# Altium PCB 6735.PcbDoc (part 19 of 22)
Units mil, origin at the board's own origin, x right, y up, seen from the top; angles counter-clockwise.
Board outline 2641.73 x 5165.35 mil, 6 copper layers (Top, Inner Layer 2, Inner Layer 3, Inner Layer 4, Inner Layer 5, Bottom), stack 35.7 mil thick; 1011 components, 790 nets, 4118 pads, 9325 vias.
Unrouted connection lines stored in the file: 4610.
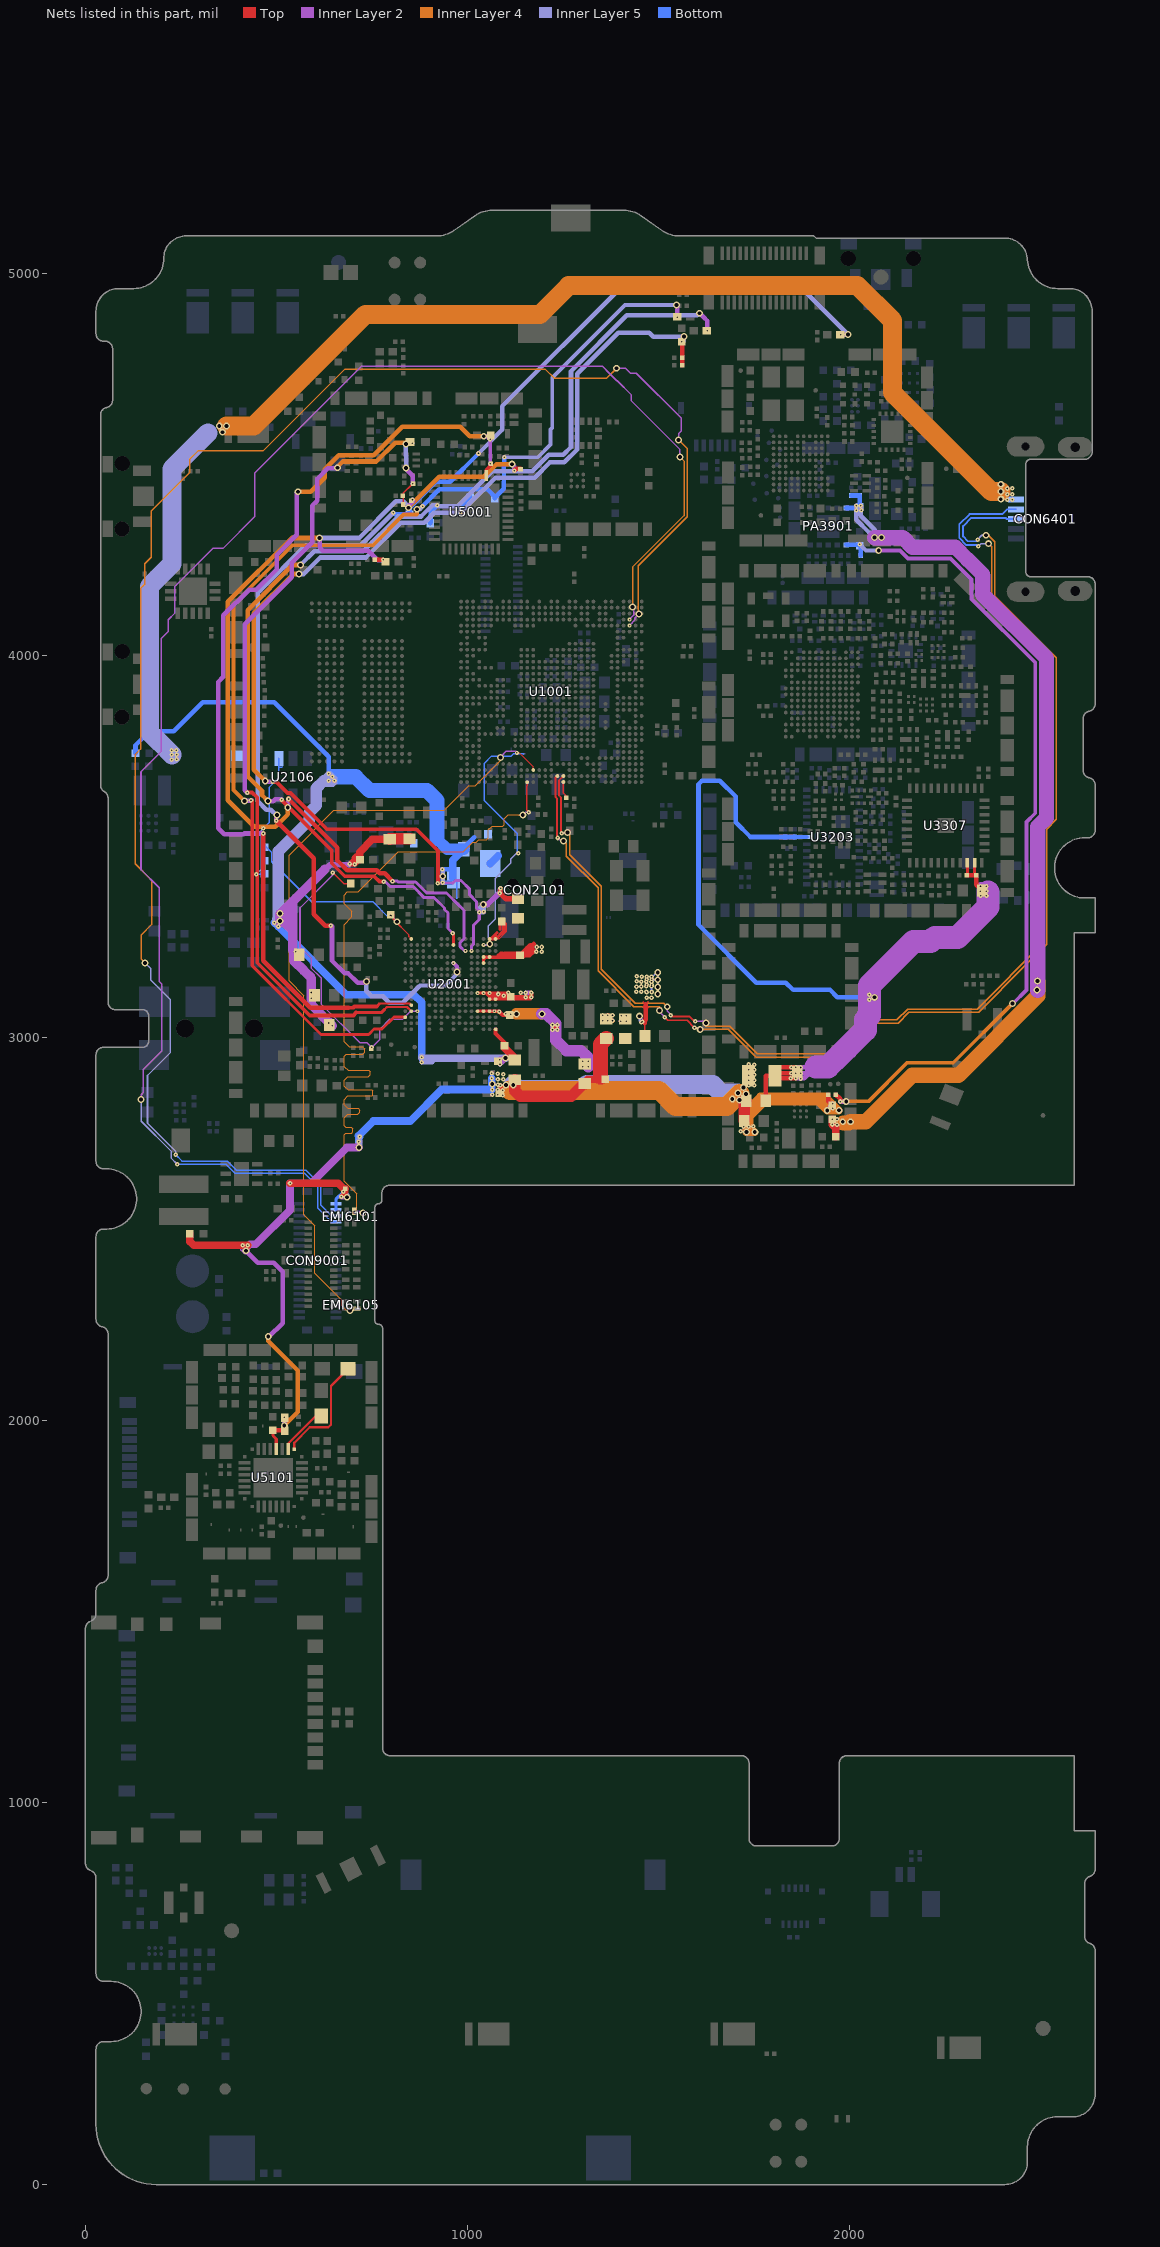
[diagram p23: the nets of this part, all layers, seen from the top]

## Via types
v1: diameter 12, hole 4, Top to Inner Layer 2, 3329 vias
v2: diameter 12, hole 4, Inner Layer 5 to Bottom, 3071 vias
v3: diameter 18, hole 10, Inner Layer 2 to Inner Layer 5, 1928 vias
v4: diameter 10, hole 4, Top to Inner Layer 2, 525 vias
v5: diameter 20, hole 12, Top to Bottom, 472 vias

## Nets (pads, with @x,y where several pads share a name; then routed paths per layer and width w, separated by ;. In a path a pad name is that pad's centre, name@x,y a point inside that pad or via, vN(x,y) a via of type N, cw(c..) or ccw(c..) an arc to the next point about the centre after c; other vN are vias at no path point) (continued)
TDP2: EMI6105.4 U1001.N3 | length 2074
  Top w3: U1001.N3@1171.71,3700.77 1171.71,3709.19 1135.41,3745.49 v4@1132.45,3745.49 ; v4@1132.45,3745.49 1129.95,3746.49 v4(1128.95,3745.49) v4@1132.45,3745.49
  Top w4: v1(707.46,2291.01) 707.46,2291.25 EMI6105.4@710.07,2291.25
  Inner Layer 2 w4: v3(692.08,2287.11) 695.99,2291.01 v1(707.46,2291.01) ; v3(1085.95,3733.49) 1088.95,3733.49 1088.95,3738.49 1100.95,3750.49 1125.95,3750.49 1129.95,3746.49 v4(1128.95,3745.49)
  Inner Layer 4 w3: v3(692.08,2287.11) 692.08,2288.41 681.58,2288.41 670.27,2299.72 670.27,2314.18 599.66,2384.8 599.66,2509.12 571.3,2537.48 571.3,3110.32 569.4,3112.22 532.58,3149.04 532.58,3478.11 650.01,3595.55 938.95,3595.55 1003.23,3659.83 1019.8,3659.83 1085.95,3725.98 v3(1085.95,3733.49)
TDP3: EMI6101.4 U1001.M1 | length 2022.2
  Top w4: v1(703.3,2547.09) EMI6101.4@703.8,2546.59 ; U1001.M1@1155.96,3669.27 1155.96,3660.61 1154.95,3659.6 1154.95,3595.44 v1(1160.3,3590.09)
  Inner Layer 2 w4: v1(703.3,2547.09) 715.3,2547.09 720.3,2542.09 v3(726.3,2542.09) ; v3(1144.3,3583.09) 1152.08,3590.86 1160.3,3590.86 v1(1160.3,3590.09)
  Inner Layer 4 w3: v3(726.3,2542.09) 716.95,2542.09 709.3,2549.74 709.3,2592.83 676.8,2625.33 676.8,2746.83 681.08,2751.11 696.23,2751.11 699.95,2754.83 699.95,2761.83 695.67,2766.11 680.95,2766.11 677.3,2769.76 677.3,2790.83 686.57,2800.11 712.08,2800.11 718.08,2806.11 718.08,2811.11 713.08,2816.11 686.35,2816.11 677.3,2825.16 677.3,2838.83 686.57,2848.11 750.23,2848.11 751.95,2849.83 751.95,2861.83 749.67,2864.11 687.35,2864.11 677.3,2874.16 677.3,2888.83 686.57,2898.11 739.73,2898.11 744.95,2903.33 744.95,2910.83 740.67,2915.11 687.08,2915.11 677.3,2924.89 677.3,2951.81 682.57,2957.09 725.31,2957.09 730.31,2962.09 730.31,2971.09 724.31,2977.09 689.57,2977.09 677.3,2989.36 677.3,3296.58 697.08,3316.36 697.08,3331.38 676.8,3351.66 676.8,3373.83 685.07,3382.11 713.18,3382.11 818.18,3487.11 988.08,3487.11 1013.06,3512.09 1021.86,3512.09 1028.86,3519.09 1049.3,3519.09 1054.3,3524.09 1054.3,3544.53 1063.86,3554.09 1092.3,3554.09 1095.3,3557.09 1095.3,3573.21 1105.57,3583.49 1133.35,3583.49 1133.75,3583.09 v3(1144.3,3583.09)
TX_N: L5102.1 U5101.17 | length 296.4
  Top w6: U5101.17@546.42,1923.99 546.42,1940.43 587.08,1981.09 635.21,1981.09 642.31,1988.19 642.31,2089.59 L5102.1@686.81,2134.09
TX_P: L5101.1 U5101.18 | length 131.9
  Top w6: U5101.18@530.67,1923.99 530.67,1938.82 601.31,2009.47 615.94,2009.47 615.94,2010.59 L5101.1@617.31,2010.59
URXD0: CON9001.5 U1001.AJ27 | length 4589.7
  Inner Layer 2 w4: v3(1389.76,4752.09) 1412.68,4752.09 1425.68,4739.09 1441.15,4739.09 1559.27,4620.97 1559.27,4588.64 1552.01,4581.38 v3(1552.01,4564.43) ; v4(1423.68,4078.72) 1430.95,4085.99 1430.95,4087.56 1437.11,4093.71 1437.11,4097.88 v3(1448.31,4109.09) v3@1448.54,4108.86
  Inner Layer 4 w4: v3(156.07,3196.06) 146.31,3205.81 146.31,3269.82 173.1,3296.61 173.1,3412.72 130.31,3455.51 130.31,3741.71 144.31,3755.71 144.31,4176.2 155.31,4187.2 155.31,4240.33 172.31,4257.33 172.31,4378.59 272.95,4479.23 272.95,4514.36 294.42,4535.83 464.56,4535.83 677.82,4749.09 1203.59,4749.09 1226.85,4725.83 1363.5,4725.83 v3(1389.76,4752.09) ; v3(1448.31,4109.09) 1446.19,4111.21 1446.19,4120.97 1446.31,4121.09 1446.31,4235.45 1574.31,4363.45 1574.31,4542.13 v3(1552.01,4564.43)
  Inner Layer 5 w4: v3(156.07,3196.06) 171.31,3180.81 171.31,3151 222.31,3100 222.31,2961.78 162.31,2901.78 162.31,2776.78 235.98,2703.11 v2(235.98,2694.33)
  Bottom w4: v2(235.98,2694.33) 252.61,2677.69 370.71,2677.69 394.31,2654.09 576.61,2654.09 615.31,2615.39 615.31,2563.07 638.29,2540.1 644.25,2534.16 655.53,2534.16 CON9001.5@655.53,2535.2
USB_DM: CON6401.2 U1001.V2 | length 3377
  Top w5: v1(1245.95,3535.09) 1243.95,3537.09 1243.95,3629.49 1238.95,3634.49 1238.95,3673.52 U1001.V2@1250.45,3685.02 ; v1(1531.14,3059.68) 1534.69,3056.13 1579.16,3056.13 1592.2,3043.09 v1(1595.82,3043.09)
  Inner Layer 2 w4: v1(1245.95,3535.09) 1245.95,3536.09 1260.95,3536.09 v3(1260.95,3537.09) ; v3(1522.21,3081.4) 1522.21,3070.19 1531.31,3061.09 v1(1531.14,3059.68) ; v1(1595.82,3043.09) 1619.31,3043.09 v3(1623.31,3039.09)
  Inner Layer 4 w3.5: v3(1260.95,3537.09) 1261.97,3537.09 1266.95,3532.11 1266.95,3479.19 1349.95,3396.19 1349.95,3179.24 1438.36,3090.83 1512.78,3090.83 v3(1522.21,3081.4) ; v3(1623.31,3039.09) 1623.31,3031.69 1624.3,3030.7 1685.59,3030.7 1758.17,2958.11 1944.3,2958.11 2033.16,3046.97 2122.41,3046.97 2150.81,3075.38 2333.04,3075.38 2506.18,3248.52 2506.18,3549.65 2531.81,3575.28 2531.81,3991.57 2370.81,4152.57 2370.81,4284.59 v3(2362.31,4293.09)
  Inner Layer 5 w4: v2(2336.31,4286.09) 2343.31,4293.09 v3(2362.31,4293.09)
  Bottom w4.6: CON6401.2@2422.36,4383.08 CON6401.2@2434.95,4383.08
  Bottom w5: v2(2336.31,4286.09) 2332.9,4289.5 2304.56,4289.5 2286.06,4308 2286.06,4343.58 2312.99,4370.5 2398.96,4370.5 2411.54,4383.08 CON6401.2@2434.95,4383.08
USB_DP: CON6401.3 U1001.U2 | length 3382.1
  Top w5: U1001.U2@1234.7,3685.02 1232.95,3685.01 1229.95,3682.01 1229.95,3630.49 1233.31,3627.12 1233.31,3523.09 v1(1235.31,3523.09) ; v1(1515.72,3054.07) 1523.71,3046.09 1574.46,3046.09 v1(1593.46,3027.09)
  Inner Layer 2 w4: v1(1235.31,3523.09) 1239.57,3518.83 1247.21,3518.83 v3(1250.95,3515.09) ; v3(1501.94,3071.59) 1497.2,3072.96 1497.06,3072.82 1506.78,3063.1 1506.78,3063.02 v1(1515.72,3054.07) ; v1(1593.46,3027.09) 1603.31,3027.09 v3(1608.31,3022.09)
  Inner Layer 4 w3.5: v3(1250.95,3515.09) 1258.4,3507.65 1258.4,3475.73 1341.45,3392.67 1341.45,3361.22 ; 1341.42,3361.19 1341.42,3175.91 1341.26,3175.91 1435.08,3082.08 1501.28,3082.08 1505.02,3078.34 1505.02,3077.1 1501.94,3074.02 v3(1501.94,3071.59) ; v3(1608.31,3022.09) 1608.41,3022.19 1682.08,3022.19 1754.65,2949.61 1947.82,2949.61 2036.68,3038.47 2125.93,3038.47 2154.33,3066.88 2336.59,3066.88 2456.85,3187.13 2514.68,3244.96 2514.68,3546.09 2540.31,3571.72 2540.31,3995.09 2379.31,4156.09 2379.31,4298.36 2362.59,4315.09 v3(2356.31,4315.09)
  Inner Layer 5 w4: v2(2334.31,4303.09) 2333.81,4303.59 2345.31,4315.09 v3(2356.31,4315.09)
  Bottom w5: v2(2334.31,4303.09) v2(2334.31,4303.09) 2330.63,4299.5 2308.7,4299.5 2296.14,4312.07 2296.14,4339.25 2317.39,4360.5 2408.05,4360.5 2411.06,4357.49 CON6401.3@2434.95,4357.49
USB_VRT_P0: R1201.1 U1001.V1 | length 43.9
  Top w4: U1001.V1@1250.45,3669.27 1250.45,3640.49 1257.95,3632.98 1257.95,3630.49 R1201.1@1257.95,3628.49
UTXD0: CON9001.7 U1001.AJ28 | length 4388.3
  Top w4: v4(1423.68,4094.47) 1423.61,4094.53 1422.25,4096.02 v4(1423.68,4094.47) v4(1423.68,4094.47)
  Inner Layer 2 w4: v3(145.71,2838.7) 145.71,2851.36 151.28,2856.94 151.28,2917.53 199.35,2965.6 199.35,3141.34 193.28,3147.42 193.28,3392.63 145.31,3440.59 145.31,3696.09 198.31,3749.09 198.31,4045.22 216.31,4063.22 216.31,4094.04 233.95,4111.68 233.95,4182 332.78,4280.83 359.57,4280.83 442.95,4364.21 442.95,4478 722.04,4757.09 1352.91,4757.09 1362.31,4747.68 1362.31,4747.01 1390.23,4719.09 1391.56,4719.09 1428.31,4682.34 1428.31,4666.69 1555.31,4539.69 v3(1555.31,4520.13) ; v4(1423.68,4094.47) 1423.26,4095.14 1433.95,4105.82 1433.95,4127.09 v3(1431.31,4127.09)
  Inner Layer 4 w4: v3(1431.31,4127.09) 1431.31,4231.78 1566.31,4366.78 1566.31,4509.13 v3(1555.31,4520.13)
  Inner Layer 5 w4: v3(145.71,2838.7) 145.71,2782.07 224,2703.77 224,2701.55 ; 223.98,2701.52 223.98,2685.61 v2(239.9,2669.68)
  Bottom w4: v2(239.9,2669.68) 367.4,2669.68 391,2646.09 573.3,2646.09 607.31,2612.08 607.31,2555.35 644.25,2518.41 655.53,2518.41 CON9001.7@655.53,2519.45
VBAT: C2007.1 C9001.1 CON2101.1 CON9001.1 CON9001.3 D2103.K R2036.1 R2037.1 R2045.1 R2047.1 R2048.2 R2098.1 R2099.1 R2135.2 R2140.2 R2308.1 R2316.1 R2405.1 R2408.1 R3239.2 SH2009.1 SH2010.1 SH2011.1 SH2012.1 SH2013.1 SH2014.1 SH5111.1 VR2101.1 | length 8783.8
  Top w4: R2308.1@272.37,2488.41 R2308.1@272.95,2487.83 ; v1(520.68,2007.69) 520.96,2007.41 SH5111.1@520.96,2006.49 ; v1(550.21,3225.31) 552.31,3226.09 559.36,3219.04 R2099.1@559.36,3217.83 ; v1(590.95,3103.83) 598.95,3111.83 R2037.1@599.36,3111.83 592.36,3118.83 v1(590.95,3118.83) ; v1(636.17,3039.02) 638.76,3039.02 R2098.1@643.95,3033.83 ; R2098.1@637.72,3033.83 R2098.1@643.95,3033.83 ; v1(691.1,3455.08) 691.1,3454.99 704.6,3454.99 v1(704.6,3454.89) ; R2048.2@1079.31,2938.76 R2048.2@1080.16,2938.91 ; v1(1084.08,2943.12) 1084.23,2942.98 R2048.2@1080.16,2938.91 ; v1(1084.61,2930.81) 1084.61,2934.47 R2048.2@1080.31,2938.76 ; SH2012.1@1120.31,3372.09 1123.44,3372.09 SH2012.1@1131.45,3364.08 1130.31,3362.94 SH2012.1@1130.31,3352.09 ; v1(1456.95,3041.83) 1458.45,3043.33 1463.72,3038.06 C2007.1@1463.72,3005.09 ; 1459.31,3079.09 1459.31,3081.68 1465.72,3088.09 ; 1459.31,3094.09 1465.31,3088.09 1465.72,3088.09 ; 1471.81,3094.09 1471.72,3094.09 ; 1472.31,3079.09 1465.72,3085.68 1465.72,3088.09 ; R3239.2@1722.31,2917.56 1734.63,2905.24 R3239.2@1734.63,2902.13 ; R3239.2@1735.08,2899.06 1735.08,2900.13 R3239.2@1735.08,2900.58 ; R2098.1@643.95,3033.83 v1(645.95,3031.83) 645.95,3032.83 644.95,3033.83 R2098.1@643.95,3033.83 ; R2048.2@1080.16,2938.91 1080.31,2938.91 R2048.2@1080.31,2938.76 ; R2048.2@1080.16,2938.91 R2048.2@1080.31,2938.76 ; 1465.72,3088.09 1471.72,3094.09 ; 1465.72,3088.09 1471.72,3094.09 ; R3239.2@1734.63,2902.13 v1(1735.08,2902.58) 1735.08,2901.75 1735.08,2901.03 R3239.2@1735.08,2900.58 ; R3239.2@1734.63,2902.13 R3239.2@1734.63,2900.58 R3239.2@1735.08,2900.58
  Top w10: v1(704.6,3454.89) v1@705.25,3455.09 ; v1@705.3,3455.13 705.16,3455.53 705.29,3455.1 705.56,3454.84 705.81,3455.09 716.81,3466.09 717.06,3466.34 R2045.1@717.31,3466.34
  Top w12: v1(669.29,2583.91) 682.34,2596.96 682.34,2603.11 C9001.1@679.95,2605.49 ; 717.31,3486.09 702.11,3470.89 702.11,3466.09 ; SH2014.1@1083.58,2855.15 1084.81,2855.15 v1(1084.81,2876.65) ; v1(1084.14,3379.1) 1084.14,3380.83 v1@1085.95,3380.83 ; v1@1085.95,3391.13 v1@1085.95,3380.83 ; 1102.62,3364.08 v1@1085.95,3380.75 ; 1463.72,3038.06 1463.72,3045.59 1465.72,3047.59 1465.72,3088.09 ; v1(1735.08,2902.58) R3239.2@1735.47,2902.77 ; 702.11,3466.09 697.76,3461.74 v1(691.1,3455.08) 693.31,3455.09 705.25,3455.09 705.31,3455.09 705.81,3455.09 707.31,3455.09 R2045.1@718.31,3466.09 717.31,3466.09 716.81,3466.09 702.11,3466.09 ; v1@1085.95,3380.75 v1@1085.95,3380.83 ; v1@1085.95,3380.75 1086.03,3380.75 v1@1085.95,3380.83 ; R3239.2@1734.63,2900.58 1735.08,2900.13 1739.08,2896.13 1739.08,2885.58 1738.83,2886.45 1737.67,2890.35 1735.08,2899.06 R3239.2@1734.63,2900.58 ; R3239.2@1734.63,2900.58 1735.08,2901.75 1735.36,2902.47 R3239.2@1735.47,2902.77 ; R3239.2@1734.63,2900.58 1735.08,2901.03 R3239.2@1738.08,2904.03 ; R3239.2@1735.47,2902.77 1738.08,2909.58 R3239.2@1738.08,2904.03 ; R3239.2@1735.47,2902.77 R3239.2@1738.08,2904.03
  Top w15: v1@1085.95,3380.75 1085.45,3380.25 1085.45,3379.1 1100.47,3364.08 1102.62,3364.08 SH2012.1@1131.45,3364.08
  Top w20: R2308.1@272.95,2487.83 272.95,2467.5 282.95,2457.5 384.06,2457.5 ; v1(411.56,2457.5) 384.06,2457.5 ; v1(424.17,2457.63) 384.2,2457.63 384.06,2457.5 ; v1(535.24,2620.16) 661.16,2620.16 675.83,2605.49 C9001.1@679.95,2605.49 ; R2045.1@717.31,3466.09 717.31,3466.34 717.31,3486.09 750.91,3519.68 R2047.1@796.31,3519.68 ; SH2013.1@1118.95,2890.9 SH2013.1@1122.95,2890.9 ; SH2010.1@1306.31,2880.5 1306.31,2884.09 1314.31,2892.09 R2405.1@1360.31,2892.09
  Top w30: R2047.1@796.31,3519.68 796.31,3521.08 R2036.1@847.95,3521.08 ; SH2013.1@1122.95,2890.9 1122.95,2861.9 1138.02,2846.83 1270.64,2846.83 1304.31,2880.5 SH2010.1@1306.31,2880.5
  Top w40: 1347.31,2898.09 1347.31,2983.5 SH2009.1@1362.31,2998.5
  Inner Layer 2 w4: v1(411.56,2457.5) 405.91,2451.84 405.91,2446.02 408.64,2443.28 v3(419.64,2443.28) ; v3(508.77,3305.97) 500.99,3313.75 500.99,3317.15 v3(509.03,3325.18) ; 520.95,3301.93 539.2,3301.93 542.31,3298.81 ; v1@545.45,3226.09 550.21,3226.09 v1(550.21,3225.31) ; v1@636.17,3041.61 v1(636.17,3039.02) 644.66,3030.53 v1(645.95,3031.83) ; v1@1084.81,2876.61 v3(1100.35,2876.57) ; v3(1449.95,3056.83) 1456.95,3049.83 v1(1456.95,3041.83) ; v1(1481.95,3153.49) 1481.95,3152.79 v3@1497.31,3152.79 ; v3(1497.31,3133.09) v3(1497.31,3152.09) v3@1497.31,3152.79 ; v3(1497.31,3171.09) v3@1497.31,3152.79
  Inner Layer 2 w12: v3(419.64,2443.28) 451.14,2411.79 492.47,2411.79 515.99,2388.27 515.99,2253.9 479.75,2217.65 v3(478.31,2219.09) ; v3(520.31,1986.09) 520.68,1986.45 v1(520.68,2007.69) ; v1(669.29,2583.91) 669.29,2583.5 684.3,2583.5 v3(684.3,2583.09) ; v1@690.51,3453.56 691.85,3454.89 v1(704.6,3454.89) ; v1@1084.1,3380.83 v1(1084.14,3379.1) v1@1084.14,3380.83 ; v1@1085.95,3380.83 v1@1084.14,3380.83 ; v1(1085.96,3391.13) 1084.14,3389.3 v1@1084.14,3380.83 ; v3(1099.31,2947.15) v3@1099.31,2945.51 ; v3@1098.61,2944.81 1090.5,2936.7 v1(1084.61,2930.81) 1084.35,2930.81 1084.35,2943.12 v1(1084.08,2943.12) 1084.08,2944.81 v3@1098.61,2944.81 ; v3@1098.61,2944.81 v3@1099.31,2945.51 ; v3@1098.61,2944.81 1099.31,2944.81 v3@1099.31,2945.51
  Inner Layer 2 w15: 625.95,3440.83 628.31,3440.83 640.57,3453.09 690.51,3453.09 v1@690.51,3453.56 ; v3(1040.95,3348.83) 1052.1,3348.83 v1@1084.1,3380.83
  Inner Layer 2 w20: v3(419.64,2443.28) 419.64,2449.9 429.62,2459.88 445.39,2459.88 535.31,2549.81 535.31,2586.18 535.24,2586.26 v1(535.24,2620.16) 591.12,2620.16 684.05,2713.09 v3(715.31,2713.09) ; 542.31,3298.81 542.31,3299.99
  Inner Layer 2 w25: v3(509.03,3325.18) v3@510.3,3325.18 ; 542.31,3298.81 542.31,3280.56 ; 625.95,3440.83 542.31,3357.19 ; v1(645.95,3031.83) 637.47,3040.32 636.17,3041.61 590.95,3086.83 v1(590.95,3103.83) v1(590.95,3118.83) 590.95,3156.24 571.45,3175.74 571.45,3175.93 545.65,3201.74 545.45,3201.74 545.45,3226.09 542.31,3229.23 542.31,3280.56 ; v3@510.3,3325.18 v3@517.12,3325.18 ; v3@510.3,3325.18 509.67,3324.54 508.77,3323.65 v3(508.77,3305.97) 508.77,3301.93 520.95,3301.93 542.31,3280.56 ; v3@510.3,3325.18 521.12,3336 ; v3@517.12,3325.18 517.64,3325.18 521.12,3321.71 ; v3@517.12,3325.18 542.31,3299.99 542.31,3321.71 ; 521.12,3321.71 542.31,3321.71 ; 521.12,3321.71 521.12,3336 ; 521.12,3336 542.31,3357.19 ; 542.31,3321.71 542.31,3357.19
  Inner Layer 4 w12: v3(478.31,2219.09) 478.31,2206.98 555.44,2129.85 555.44,2021.22 v3(520.31,1986.09)
  Inner Layer 4 w50: 1111.31,2863.09 1111.57,2862.83 1500.86,2862.83 1543.33,2820.36 1677.71,2820.36 1703.11,2845.76 1710.11,2852.76 v3@1711.96,2854.62
  Inner Layer 5 w4: 494.47,3309.33 498.88,3313.75 500.99,3313.75 504.95,3309.79 508.06,3306.68 v2@498.62,3297.25 ; v2(504.28,3291.59) 504.28,3296.53 504.28,3301.48 v3(508.77,3305.97) ; 622.9,3672.44 v2(651.47,3672.44) ; v2(1480.95,3159.83) 1482.23,3158.55 1496.04,3172.36 v3(1497.31,3171.09)
  Inner Layer 5 w6: v3(1449.95,3056.83) 1449.95,3044.71 v2(1453.66,3041)
  Inner Layer 5 w12: v2(504.28,3291.59) v2@501.81,3294.06 ; v3(508.77,3305.97) 511.24,3303.5 504.28,3296.53 v2@501.81,3294.06 ; v3(509.03,3325.18) 507.67,3326.54 504.95,3323.82 494.47,3313.33 494.47,3309.33 v2(494.47,3301.33) v2(494.47,3301.33) 498.62,3297.25 499.34,3296.53 v2@501.81,3294.06 ; v2(674.95,2597.83) 675.96,2597.83 684.3,2589.49 v3(684.3,2583.09) ; v2(880.31,2949.15) v2(880.31,2936.65) 906.81,2936.65 917.31,2947.15 ; v2(933.95,3440.83) 934.45,3440.83 934.45,3432.83 ; v2(934.95,3405.83) v3(934.95,3422.83) ; 934.45,3432.83 934.95,3432.33 v3(934.95,3422.83) ; 934.45,3432.83 934.45,3422.83 v3(934.95,3422.83) ; v2(1029.95,3328.83) 1029.95,3337.83 v3(1040.95,3348.83) 1041.45,3348.83 1041.45,3329.83 v2(1041.95,3329.83) 1041.95,3328.83 v2(1029.95,3328.83)
  Inner Layer 5 w15: v3(715.31,2713.09) 716.21,2713.09 716.21,2741.14 v2(717.11,2741.14) ; 622.9,3668.3 627.16,3664.04 646.84,3664.04 651.47,3668.67 v2(651.47,3672.44) 651.47,3677.94 v2(646.19,3683.22) 638.62,3690.79 v2(636.32,3690.79) 635.4,3690.79 622.9,3678.29 622.9,3672.44 622.9,3668.3
  Inner Layer 5 w18: v3(715.31,2713.09) v2(715.32,2728.78)
  Inner Layer 5 w20: v2(880.31,2949.15) 882.31,2947.15 917.31,2947.15 v3(1099.31,2947.15)
  Inner Layer 5 w25: v3(508.77,3305.97) 508.77,3318.24 505.43,3321.58 504.95,3322.06 508.07,3325.18 v3(509.03,3325.18)
  Inner Layer 5 w30: v3@504.95,3309.79 504.95,3322.06 504.95,3323.82 504.95,3488.67 584.93,3568.65 584.93,3589.06 603.95,3608.09 603.95,3653.49 622.9,3672.44 623.76,3673.3 v2(637,3673.3) ; v3@508.06,3306.68 v3(508.77,3305.97)
  Inner Layer 5 w50: v3(1119.31,2877.09) 1119.31,2865.09 1298.79,2865.09 1311.79,2878.09 1641.31,2878.09 1663.84,2855.56 v3(1707.31,2855.56)
  Bottom w4: R2316.1@130.95,3744.49 R2316.1@131.31,3744.13 ; v2(715.32,2728.78) 716.21,2728.78 716.21,2740.24 716.21,2741.14 v2(717.11,2741.14) ; v2@879.52,2948.36 v2(880.31,2949.15) v2(880.31,2936.65) ; R2135.2@957.95,3407.83 957.95,3414.04 R2135.2@963.4,3419.49 ; R2135.2@960.95,3419.49 R2135.2@963.4,3419.49 ; R2135.2@960.95,3440.83 963.4,3438.38 R2135.2@963.4,3419.49 ; R2140.2@971.95,3365.49 971.95,3410.94 R2135.2@963.4,3419.49 ; v2(1480.95,3134.83) 1480.95,3122.83 v2(1481.95,3120.83)
  Bottom w8: CON9001.3@655.53,2550.95 CON9001.1@655.53,2566.7 655.95,2566.69 655.95,2578.83 v2(674.95,2597.83)
  Bottom w12: R2316.1@130.95,3744.49 130.95,3765.5 167.95,3802.5 230.72,3802.5 306.72,3878.5 494.06,3878.5 637,3735.56 v2@637,3690.79 ; v2(636.32,3690.79) v2@637,3690.79 ; v2(651.47,3672.44) 651.47,3673.3 v2(637,3673.3) ; v2@651.58,3683.62 647.33,3683.62 646.93,3683.22 v2(637,3673.3) ; v2(933.95,3440.83) R2135.2@960.95,3440.83 ; v2(934.95,3405.83) 957.95,3405.83 R2135.2@957.95,3407.83 ; D2103.K@989.95,3493.72 989.95,3497.65 1017.72,3525.42 ; v2(637,3673.3) v2@637,3690.79 ; v2(637,3673.3) v2@637,3690.79
  Bottom w20: v2@494.49,3301.35 v2(504.28,3291.59) ; v2(504.28,3291.59) 682.79,3113.08 859.2,3113.08 879.52,3092.75 v2@879.52,2948.36 ; v2(715.32,2728.78) 715.32,2739.35 716.21,2740.24 v2(717.11,2741.14) 714.56,2743.69 753.37,2782.5 849.69,2782.5 932.19,2865 1063.31,2865 v2(1063.31,2894.09) ; R2135.2@960.95,3419.49 960.95,3440.83 960.95,3464.72 974.32,3478.09 D2103.K@989.95,3493.72 D2103.K@989.95,3489.78 ; CON2101.1@1059.2,3456.21 CON2101.1@1079.95,3476.95
  Bottom w30: 919.75,3520.69 946.72,3493.72 D2103.K@989.95,3493.72
  Bottom w40: v2(646.19,3683.22) 646.93,3683.22 707.18,3683.22 742.96,3647.44 893.53,3647.44 919.75,3621.22 919.75,3520.69
  other v1: 1735.31,2876.56 1749.31,2876.56 1735.08,2889.58 1749.31,2889.56 1749.31,2903.56 1735.08,2916.58 1749.31,2916.56 1749.31,2929.56 1735.31,2930.56 1468.95,3105.49 1480.95,3105.49 1468.95,3119.49 1481.95,3119.49 1468.95,3139.49 1481.95,3139.49 1468.95,3153.49
  other v2: 1092.02,2849.95 1064.62,2851.13 1078.72,2851.6 1091.84,2862.93 1064.31,2864.09 1079.31,2864.09 1079.31,2877.09 1079.31,2892.09 1093.31,2892.09 1092.94,2905.36 1078.72,2906.57 1063.3,2907.41 1441.6,3120.71 1454.3,3120.7 1466.95,3120.83 1441.75,3134.3 1454.46,3134.5 1466.95,3134.83 1454.41,3147.45 1466.95,3146.83 1480.95,3146.83 1442.03,3148.48 1455.32,3159.99 1468.48,3159.81 1441.9,3161.29
  other v3: 1711.31,2837.56 1692.31,2840.56 1728.31,2853.56 1721.31,2870.56 1064.31,2879.09 1497.31,3115.09
VBAT_NFC: C5115.2 SH5111.2 U5101.20 | length 83.7
  Top w8: C5115.2@490.31,1973.09 490.45,1972.95 490.45,1959.28 499.17,1950.55 U5101.20@499.18,1923.99
  Top w12: C5115.2@490.31,1973.09 520.36,1973.09 SH5111.2@520.96,1972.49
VBAT_RF: C3239.1 C3248.1 C3249.1 C3324.1 C3339.1 C3348.1 R3239.1 R3901.1 U3203.8 U3307.9 U3307.10 | length 2818.9
  Top w4: R3239.1@1803.53,2900.58 1803.95,2900.16 R3239.1@1803.95,2892.96
  Top w8: U3307.9@2307.35,3458.15 C3348.1@2307.35,3427.28 ; U3307.10@2326.24,3458.15 2326.24,3430 C3324.1@2330.65,3425.59 ; C3348.1@2307.35,3427.28 C3348.1@2305.65,3425.59 2307.35,3425.59 C3348.1@2307.35,3427.28
  Top w12: R3901.1@1779.67,2835.58 1779.67,2899.72 1780.53,2900.58 R3239.1@1803.53,2900.58 R3239.1@1803.53,2907.92 ; R3239.1@1803.95,2892.96 1804.95,2893.96 v1(1857.95,2893.96) ; v1(1858.95,2907.93) v1(1846.44,2907.92) R3239.1@1803.53,2907.92 ; C3239.1@1858.95,2922.94 v1(1846.73,2922.92) 1814.87,2922.92 1803.53,2911.58 R3239.1@1803.53,2907.92 ; C3348.1@2307.35,3425.59 C3324.1@2330.65,3425.59 2330.65,3401.18 C3339.1@2346.24,3385.59
  Top w20: R3239.1@1803.53,2911.58 R3239.1@1803.53,2914.58
  Top w30: R3239.1@1803.53,2900.58 R3239.1@1805.53,2900.58
  Inner Layer 2 w4: 2051.65,3102.15 2055.65,3106.15 v3(2064.81,3106.15) ; v1(2357.28,3397.06) 2357.32,3397.02 2361.63,3392.71 v1@2361.63,3381.91
  Inner Layer 2 w12: v1(1857.95,2893.96) 1880.95,2893.96 1894.93,2907.93 ; v1(1858.95,2907.93) 1894.93,2907.93 ; v1(1858.95,2922.96) 1909.95,2922.96 ; 1910.95,2923.96 1909.95,2922.96 ; 1894.93,2907.93 1909.95,2922.96
  Inner Layer 2 w20: v1(2342.07,3371.61) 2341.91,3371.61 v1@2341.91,3396.48 ; v1(2357.07,3384.28) 2356.33,3383.54 v1@2342.81,3397.06 ; v1(2357.28,3397.06) v1@2342.81,3397.06 ; v1@2357.32,3371.72 v1@2357.32,3381.07 ; v1@2357.32,3397.02 v1@2357.32,3381.07 ; 2361.63,3376.76 v1@2357.32,3381.07 ; v1(2341.75,3396.64) v1@2342.18,3397.06 ; v1(2341.75,3396.64) 2341.91,3396.64 v1@2341.91,3396.48 ; v1(2341.75,3396.64) v1@2341.91,3396.48 ; v1(2341.75,3396.64) v1@2342.18,3397.06 ; v1@2341.91,3396.48 v1@2357.32,3381.07 ; v1@2342.18,3397.06 v1@2342.49,3397.37 ; v1@2342.18,3397.06 v1@2342.49,3397.37 ; v1@2342.18,3397.06 v1@2342.81,3397.06 ; v1@2342.49,3397.37 v1@2342.81,3397.06
  Inner Layer 2 w60: 1910.95,2923.96 1911.12,2924.13 1942.8,2924.13 1973.58,2954.91 1991.46,2972.79 1992.15,2972.79 2040.31,3020.95 2040.31,3047.25 2051.65,3058.59 2051.65,3102.15 2051.65,3106.15 2051.65,3137.55 2166.66,3252.56 2211.53,3252.56 2222.15,3263.18 2282.05,3263.18 2361.63,3342.75 2361.63,3371.72 2361.63,3376.76 v1@2361.63,3381.91
  Inner Layer 5 w12: v2(2050.31,3100.15) 2058.81,3100.15 v3(2064.81,3106.15) 2064.94,3106.28 2058.57,3112.65 v2(2050.31,3112.65) v2(2050.31,3100.15)
  Bottom w4: v2(2050.31,3100.15) 2050.31,3098.65 2047.31,3098.65 2045.81,3100.15 2039.31,3106.65 2045.31,3112.65 2047.31,3114.65 2050.31,3114.65 v2(2050.31,3112.65)
  Bottom w10: C3249.1@1855.65,3525.59 U3203.8@1886.76,3525.59
  Bottom w12: C3249.1@1855.65,3525.59 C3248.1@1830.65,3525.59 1739.87,3525.59 1701.31,3564.15 1701.31,3631.65 1659.81,3673.15 1612.95,3673.15 1603.95,3664.15 1603.95,3296.01 1755.46,3144.5 1832.32,3144.5 1851.32,3125.5 1948.06,3125.5 1966.91,3106.65 2039.31,3106.65 ; v2@2045.31,3112.65 v2(2050.31,3112.65) v2(2050.31,3100.15) v2@2045.81,3100.15
  other v1: 1871.31,2893.56 1845.45,2893.92 1871.31,2907.56 1871.31,2922.56 2357.36,3371.72 2341.65,3383.96
VBAT_RF_CDMA: R3901.2 R3904.1 R3905.1 R3909.1 | length 822.7
  Top w4: R3905.1@1954.08,2823.58 1954.08,2827.56 v1(1955.31,2827.56)
  Top w12: R3904.1@1943.31,2851.56 1943.31,2834.35 R3905.1@1954.08,2823.58 R3905.1@1952.08,2823.58
  Top w30: R3909.1@1723.49,2782.58 1723.49,2835.58 R3901.2@1728.49,2835.58
  Inner Layer 2 w12: v3(1940.71,2809.96) 1949.42,2820.45 v1(1955.31,2827.56)
  Inner Layer 4 w20: 1917.71,2832.96 v3(1940.71,2809.96) v3@1940.71,2810.26 ; 1917.71,2832.96 1940.71,2832.96 v3@1940.71,2810.26 ; 1917.71,2832.96 1777.71,2832.96 1738.31,2793.56 1738.31,2766.56 v3(1751.31,2753.56) v3(1729.31,2753.56) 1729.31,2810.56 1766.31,2847.56 1934.31,2847.56 v3(1971.31,2810.56) 1971.31,2810.26 v3@1940.71,2810.26
  other v1: 1714.31,2755.56 1722.31,2767.56 1735.31,2767.56 1747.36,2768.73 1955.31,2815.56
VBAT_VBA: C2013.1 SH2013.2 U2001.A16 | length 103.4
  Top w10: U2001.A16@1073.06,3022.72 1073.06,3011.82 1097.78,2987.1 1097.78,2980.55 1096.31,2980.55 C2013.1@1096.31,2979.09
  Top w20: C2013.1@1096.31,2979.09 1096.31,2974.33 1122.95,2947.69 SH2013.2@1122.95,2942.08
VBAT_VCORE: C2014.1 SH2011.2 U2001.B4 U2001.C4 U2001.C5 | length 336.2
  Top w4: 1159.42,3215.83 1172.45,3228.86 ; 1162.95,3238.49 1165.45,3238.49 ; 1172.45,3226.49 1175.29,3226.49 v1@1175.95,3225.83 ; 1172.65,3245.68 1174.5,3243.84 1176.45,3241.88 v1@1177.33,3242.55 ; v1(1401.95,3057.83) 1401.95,3055.68 SH2011.2@1403.24,3049.68
  Top w8: U2001.C5@1041.57,3195.95 1041.56,3204.87 ; U2001.B4@1057.32,3211.7 1049.95,3211.7 ; 1041.56,3204.87 U2001.C4@1041.57,3211.7 1048.39,3211.7 ; 1041.56,3204.87 1048.39,3211.7 ; 1048.39,3211.7 1049.95,3211.7 ; 1049.95,3211.7 1050.56,3211.09 1057.32,3211.09 1075.31,3211.09 ; 1075.31,3211.09 1080.31,3216.09 ; 1075.31,3211.09 1091.81,3211.09 1096.81,3216.09 ; 1080.31,3216.09 1086.31,3222.09 1090.81,3222.09 1096.81,3216.09 ; 1080.31,3216.09 1096.81,3216.09
  Top w12: C2014.1@1142.45,3215.83 1159.42,3215.83 1161.79,3215.83 1172.45,3226.49 1172.45,3228.86 ; 1172.45,3245.68 1172.65,3245.68 ; v1(1400.95,3043.83) 1400.95,3043.06 1414.95,3043.06 v1(1414.95,3043.83) ; SH2011.2@1403.24,3049.68 SH2011.2@1412.31,3049.68 SH2011.2@1403.24,3049.68
  Top w20: 1096.81,3216.09 1099.31,3216.09 1099.57,3215.83 C2014.1@1136.95,3215.83 1142.45,3215.83 1157.86,3231.23 1158.2,3231.23 1165.45,3238.49
  Inner Layer 2 w4: v1@1402.45,3044.09 v1(1414.95,3043.83)
  other v1: 1414.95,3057.83 1179.95,3225.83 1193.95,3225.83 1180.95,3237.83 1193.95,3237.83
VBAT_VLTE: C2012.1 SH2010.2 U2001.B13 U2001.C13 U2001.D13 | length 553.9
  Top w4: v1(1100.18,3062.61) 1100.27,3062.29 1104.4,3063.49 1106.29,3063.49 C2012.1@1109.79,3059.99 ; C2012.1@1109.84,3059.99 1109.95,3059.99 C2012.1@1109.95,3059.83 ; v1(1221.95,3020.83) 1222.95,3021.83 1222.95,3024.9 1226.31,3028.27 ; v1(1221.95,3033.83) 1221.95,3028.41 1226.46,3028.42 ; 1226.46,3026.91 1226.46,3028.41 ; v1(1233.95,3020.83) 1236.95,3020.83 1236.95,3027.79 1236.33,3028.41 v1@1232.37,3028.41 ; v1(1233.95,3033.83) v1@1232.37,3028.41 ; SH2010.2@1306.31,2931.68 SH2010.2@1306.31,2932.78 ; C2012.1@1105.45,3055.99 1105.61,3055.82 C2012.1@1105.78,3055.99 ; C2012.1@1105.45,3055.99 C2012.1@1105.78,3055.99 ; C2012.1@1105.45,3055.99 C2012.1@1107.7,3057.91 ; C2012.1@1105.78,3055.99 1109.95,3055.99 C2012.1@1109.95,3059.83 ; C2012.1@1105.78,3055.99 C2012.1@1107.7,3057.91 ; C2012.1@1107.7,3057.91 C2012.1@1109.95,3059.83 ; C2012.1@1107.7,3057.91 1109.62,3059.83 C2012.1@1109.79,3059.99 ; C2012.1@1109.81,3059.97 C2012.1@1109.95,3059.83 ; C2012.1@1109.82,3060.01 C2012.1@1111.02,3060.9 ; C2012.1@1109.82,3060.01 C2012.1@1111,3060.88 ; C2012.1@1109.95,3059.83 1110.61,3059.83 C2012.1@1112.06,3058.37 ; C2012.1@1109.95,3059.83 1110.57,3059.4 C2012.1@1112.06,3058.37 ; C2012.1@1109.95,3059.83 1110.94,3060.81 C2012.1@1111,3060.88 ; C2012.1@1111.02,3060.9 v1(1112.21,3061.77) ; C2012.1@1111,3060.88 v1(1112.21,3061.77) ; C2012.1@1111.02,3060.9 1113.61,3063.49 1114.95,3063.49 v1(1112.21,3061.77) ; C2012.1@1112.06,3058.37 1111.97,3056.24 1111.96,3055.99 1111.91,3054.9 1112.67,3054.95 1114.29,3055.06 1114.6,3055.99 1114.68,3056.24 1113.95,3056.49 C2012.1@1112.06,3058.37 ; C2012.1@1112.06,3058.37 1112.12,3059.73 v1(1112.21,3061.77) ; 1226.31,3028.27 1226.31,3022.09 1226.46,3028.41 ; 1226.31,3028.27 1226.46,3028.42 ; 1226.31,3028.27 1226.46,3028.41 ; 1226.46,3028.41 v1@1232.37,3028.41 ; 1226.46,3028.42 1226.32,3033.63 1226.32,3033.95 1226.31,3034.09 1226.46,3033.94 1226.46,3028.42 ; SH2010.2@1306.31,2932.78 1305.42,2932.78 1300.21,2937.99 v1(1301.31,2939.09) 1306.31,2939.09 SH2010.2@1306.31,2932.78
  Top w8: U2001.D13@1025.82,3069.96 U2001.C13@1041.57,3069.96 U2001.B13@1057.32,3069.96
  Top w10: U2001.B13@1057.32,3069.96 1069.95,3069.96 1081.45,3069.96 v1@1082.57,3068.84 ; C2012.1@1109.81,3059.97 C2012.1@1109.62,3059.83 ; C2012.1@1109.84,3059.99 1110.94,3060.81 v1(1112.21,3061.77) ; C2012.1@1109.95,3059.83 C2012.1@1109.62,3059.83 ; v1@1082.57,3068.84 v1(1082.95,3068.83) ; v1@1082.57,3068.84 1081.97,3068.85 v1@1082.58,3068.84 ; v1@1082.58,3068.84 v1(1082.95,3068.83) ; v1@1082.58,3068.84 v1@1085.95,3065.46 ; v1(1082.95,3068.83) 1085.95,3065.83 v1@1085.95,3065.46 ; v1@1085.95,3065.46 1091.58,3059.83 1100.18,3059.83 C2012.1@1109.62,3059.83
  Inner Layer 2 w4: v1(1221.95,3033.83) 1225.85,3037.73 v1@1230.95,3037.73
  Inner Layer 2 w30: v3(1194.1,3062.83) 1205.85,3062.83 1230.95,3037.73 1230.95,3033.83 1230.95,2994.18 1258.3,2966.83 1296.31,2966.83 1312.68,2950.45 1315.31,2947.82 v1(1315.31,2939.09) v1(1315.31,2925.09)
  Inner Layer 4 w30: v3(1127.4,3062.85) 1127.64,3063.09 1158.31,3063.09 1158.31,3062.83 v3(1194.1,3062.83)
  other v1: 1301.31,2925.09
  other v4: 1069.95,3069.83
VBAT_VPROC: C2011.1 SH2009.2 U2001.A11 U2001.B10 U2001.B11 U2001.C10 U2001.D10 | length 566.1
  Top w4: C2011.1@1112.95,3107.83 1114.6,3107.83 1116.39,3106.04 1122.61,3099.82 1165.04,3099.82 1165.95,3100.73 v1(1165.95,3105.99) ; v1(1151.54,3106.04) v1@1160.36,3106.04 ; v1@1165.31,3105.35 v1(1165.95,3105.99) ; v1@1166.31,3105.63 v1(1165.95,3105.99)
  Top w8: v4(1025.82,3117.21) v4(1041.57,3117.21) 1047.95,3117.21 ; 1047.95,3117.21 1057.31,3107.85 ; 1047.95,3117.21 v4(1057.32,3117.21) ; U2001.B11@1057.32,3101.46 U2001.A11@1073.06,3101.46 ; U2001.B11@1057.32,3101.46 U2001.A11@1073.06,3101.46 ; U2001.B11@1057.32,3101.46 1060.51,3104.65 1057.31,3107.85 ; U2001.B11@1057.32,3101.46 1057.31,3107.85 ; 1057.31,3107.85 1057.31,3108.83 ; 1057.31,3108.83 v4(1057.32,3117.21) ; 1057.31,3108.83 1103.95,3108.83 C2011.1@1107.95,3112.83 ; v4(1057.32,3117.21) 1061.69,3112.83 C2011.1@1107.95,3112.83 ; v4(1057.32,3117.21) C2011.1@1103.57,3117.21 ; v4(1057.32,3117.21) 1079.95,3117.21 1093.95,3117.21 C2011.1@1103.57,3117.21 ; U2001.A11@1073.06,3101.46 U2001.A11@1073.06,3101.83 ; U2001.A11@1073.06,3101.46 U2001.A11@1073.06,3101.83 ; U2001.A11@1073.06,3101.83 1112.95,3101.83 1112.95,3106.04 C2011.1@1112.95,3107.83 ; C2011.1@1103.57,3117.21 1104.45,3116.33 C2011.1@1107.95,3112.83 ; C2011.1@1107.95,3112.83 C2011.1@1112.95,3107.83 ; C2011.1@1107.95,3112.83 1109.78,3114.66 C2011.1@1112.95,3107.83
  Top w12: C2011.1@1112.95,3106.04 1116.39,3106.04 v1(1151.54,3106.04) ; v1@1160.36,3106.04 1165.89,3106.04 v1(1165.95,3105.99) v1(1165.95,3118.49) ; SH2009.2@1362.31,3049.68 1361.7,3049.07 SH2009.2@1359.82,3047.18 ; v1(1365.95,3044.83) v1(1378.95,3044.83) 1366.16,3043.22 1364.05,3042.95 SH2009.2@1359.82,3047.18 ; v1(1366.95,3058.83) 1359.98,3052.35 1359.9,3052.27 1359.43,3051.84 1357.22,3049.78 SH2009.2@1359.82,3047.18
  Inner Layer 2 w12: v1(1151.45,3118.49) v1(1165.95,3118.49)
  other v1: 1352.95,3044.83 1353.95,3058.83 1378.95,3058.83 1093.95,3110.83 1079.95,3114.83 1105.95,3117.83 1138.95,3117.83
VBAT_VSYS: C2015.1 SH2012.2 U2001.A1 U2001.B1 | length 218.4
  Top w4: U2001.A1@1073.06,3258.94 1081.63,3258.94 1101.18,3278.48 1101.18,3299.06 C2015.1@1092.75,3307.49
  Top w8: U2001.B1@1057.32,3258.94 U2001.B1@1060.2,3258.94 ; 1077.09,3275.83 U2001.B1@1060.2,3258.94 ; 1084.95,3283.17 1084.95,3299.99 C2015.1@1089.45,3304.49 1094.45,3299.49 1094.45,3280.33 U2001.A1@1073.06,3258.94 ; U2001.B1@1060.2,3258.94 U2001.A1@1073.06,3258.94 ; U2001.A1@1073.06,3258.94 1073.06,3271.28 U2001.A1@1073.06,3258.94
  Top w15: SH2012.2@1131.45,3307.24 SH2012.2@1131.45,3312.9
VBATREF: C2056.1 R2103.2 U2001.P13 | length 821.1
  Top w4: v1(647.37,3432.21) 675.75,3403.83 R2103.2@693.95,3403.83 ; v1(748.94,2975.09) 748.56,2974.71 748.56,2973.84 C2056.1@747.31,2972.59 ; C2056.1@747.31,2972.59 C2056.1@747.31,2972.09 747.06,2972.09 747.06,2972.34 C2056.1@747.31,2972.59
  Inner Layer 2 w4: v1(647.37,3432.21) 650.34,3429.24 561.31,3340.22 561.31,3237.74 590.31,3208.74 590.31,3183.14 616.31,3157.14 616.31,3088.88 718.1,2987.09 736.94,2987.09 v1(748.94,2975.09) 770.31,2996.46 770.31,3023.09 796.31,3049.09 829.7,3049.09 850.57,3069.96 v4(868.34,3069.96)
VBUS: C2101.2 CON6401.1 R2032.1 R2192.1 U2106.4 | length 3834.6
  Inner Layer 4 w50: v3(368.95,4600.83) 440.46,4600.83 732.72,4893.09 1189.55,4893.09 1264.55,4968.09 2020.04,4968.09 2111.31,4876.81 2111.31,4688.33 2370.16,4429.49 v3(2394.95,4429.49)
  Inner Layer 5 w4: v2(446.95,3428.49) 459.37,3440.91 459.37,3542.15 v2(465.31,3548.09)
  Inner Layer 5 w50: v2(226,3740.77) 226,3741.69 196.6,3771.09 196.22,3771.09 167.31,3799.99 167.31,4181.14 225.95,4239.78 225.95,4488.57 320.21,4582.83
  Bottom w4: v2(446.95,3428.49) 468.31,3428.49 R2192.1@468.31,3429.09 469.31,3430.09 R2032.1@469.31,3463.09 ; v2(465.31,3548.09) 481.45,3564.23 481.45,3656.17 505.91,3680.63 505.91,3709.62 ; U2106.4@505.91,3731.3 505.91,3709.62 ; 514.33,3709.03 513.39,3708.09 507.44,3708.09 505.91,3709.62
  other v2: 225.95,3727.83 238.95,3728.83 238.95,3740.83 225.95,3752.83 237.95,3752.83 2411.95,4408.49 2424.95,4408.49 2411.95,4422.49 2424.95,4422.49 2411.95,4437.49 2424.95,4438.49
  other v3: 2394.95,4409.49 2394.95,4448.49 358.95,4584.83 349.95,4600.83
VCAM_AF_PMU: R6204.2 R6205.2 U2001.H5 | length 3514.5
  Top w12: v1(499.31,3568.09) 597.31,3470.09 597.31,3323.46 627.69,3293.09 v1(641.91,3293.09)
  Inner Layer 2 w10: v4(962.83,3195.95) 972.31,3186.46 v3(972.31,3172.09)
  Inner Layer 2 w12: v1(499.31,3568.09) 499.31,3581.52 v3(500.83,3583.03) ; v1(641.91,3293.09) 644.31,3293.09 644.95,3292.45 644.95,3202.2 678.33,3168.83 687.04,3168.83 712.04,3143.83 734.95,3143.83 v3(734.95,3147.83) ; v1(1976.31,4840.09) v3(1995.31,4840.09)
  Inner Layer 5 w10: 873.31,3135.09 875.31,3137.09 941.77,3137.09 972.31,3167.63 v3(972.31,3172.09)
  Inner Layer 5 w12: v3(500.83,3583.03) 499.92,3582.13 484.95,3597.09 473.4,3597.09 451.31,3619.18 451.31,4164.09 576.24,4289.02 720.48,4289.02 v2(805.43,4373.97) ; v3(734.95,3147.83) 734.31,3147.83 734.31,3123.22 748.44,3109.09 777.71,3109.09 794.71,3092.09 830.31,3092.09 873.31,3135.09 ; v2(1028.31,4529.09) 1089.95,4590.72 1089.95,4652.43 1401.35,4963.83 1871.57,4963.83 v3(1995.31,4840.09)
  Bottom w12: v2(805.43,4373.97) 808.91,4370.49 R6204.2@847.95,4370.49 ; R6204.2@847.95,4369.49 R6204.2@847.95,4370.49 ; v2(1028.31,4529.09) 954.72,4455.5 916.96,4455.5 847.95,4386.49 R6204.2@847.95,4370.49
VCAM_IO_PMU: R1202.1 R1203.1 R6202.2 R6207.2 U2001.E3 | length 3026.8
  Top w4: v4(1010.07,3227.44) 1010.34,3227.44 1010.2,3227.58 v4(1010.07,3227.44)
  Top w10: v1(489.95,3669.83) 499.61,3669.83 528.35,3641.09 536.73,3641.09 631.73,3546.09 865.67,3546.09 921.98,3489.78 v1(921.98,3405.09)
  Top w12: v1(1560.31,4821.09) 1560.95,4820.45 R1202.1@1560.95,4779.83 R1203.1@1560.95,4759.83
  Inner Layer 2 w8: v1(921.98,3405.09) 961.02,3405.09 968.02,3412.09 982.38,3412.09 1005.31,3389.16 1005.31,3374.52 1023.31,3356.52 1023.31,3339.73 1030.31,3332.73 1030.31,3309.99 1015.31,3294.99 1015.31,3245.09 1010.07,3239.85 v4(1010.07,3227.44)
  Inner Layer 2 w12: v3(470.31,3672.09) 470.31,3669.83 v1(489.95,3669.83) ; v1(1560.31,4821.09) 1563.31,4821.09 1563.31,4835.09 v3(1566.3,4835.09)
  Inner Layer 4 w12: v3(470.31,3672.09) 440.81,3701.59 440.81,4111.09 543.55,4213.83 v3(558.95,4213.83)
  Inner Layer 5 w12: v3(558.95,4213.83) 570.98,4213.83 614.14,4256.99 734.13,4256.99 825.23,4348.09 886.31,4348.09 912.31,4374.09 v2(982.31,4374.09) 1001.31,4393.09 1001.31,4394.51 1072.89,4466.09 1175.28,4466.09 1215.28,4506.09 1252.94,4506.09 1286.31,4539.46 1286.31,4737.8 1393.6,4845.09 1474.58,4845.09 1485.58,4834.09 1566.3,4834.09 v3(1566.3,4835.09)
  Bottom w12: v2(982.31,4374.09) 982.31,4390.85 1006.45,4414.99 R6202.2@1006.45,4413.99
VCAMA_PMU: R6201.2 R6206.2 U2001.T14 | length 3171.3
  Top w4: v1(1548.31,4886.09) 1547.31,4887.09 R6206.2@1548.31,4887.09
  Top w8: v1(433.14,3621.76) 434.95,3621.83 436.31,3620.47 436.31,3189.09 616.31,3009.09 740.84,3009.09 754.84,3023.09 775.94,3023.09 807.06,3054.22 U2001.T14@836.84,3054.22
  Inner Layer 2 w12: v3(416.31,3619.83) 416.31,3620.83 434.95,3620.83 434.95,3621.76 v1(433.14,3621.76) ; v3(1545.95,4917.83) 1548.31,4915.47 v1(1548.31,4886.09)
  Inner Layer 4 w10: v3(416.31,3619.83) 387.31,3648.83 387.31,4134.73 541.52,4288.94 752.25,4288.94 832.39,4369.07 865.89,4369.07 867.75,4370.93 v3(867.75,4383.09)
  Inner Layer 5 w10: v2(1095.57,4518.83) 1096.59,4519.34 1114.06,4519.34 ; 1114.09,4519.31 1183.56,4519.31 1216.43,4552.19 1216.43,4592.16 1221.51,4597.24 1221.51,4728.15 1411.19,4917.83 v3(1545.95,4917.83)
  Inner Layer 5 w12: v3(867.75,4383.09) 874.28,4383.09 v2(881.92,4390.73)
  Bottom w10: 1094.9,4455.49 1094.9,4487.47
  Bottom w12: v2@883.31,4393.09 925.31,4435.09 1051.8,4435.09 R6201.2@1072.56,4414.33 ; R6201.2@1071.31,4412.09 R6201.2@1071.31,4413.09 ; 1094.9,4455.49 1094.9,4436.68 R6201.2@1072.56,4414.33 ; 1094.9,4487.47 1095.4,4504.09 1095.4,4518.16 1095.82,4518.58 v2(1095.57,4518.83) ; R6201.2@1071.31,4413.09 1071.31,4414.33 R6201.2@1072.56,4414.33 ; R6201.2@1071.31,4413.09 R6201.2@1072.56,4414.33
VCAMD_PMU: R6203.2 R6209.2 U2001.H2 | length 2965.7
  Top w8: v1(960.95,3273.83) 962.82,3271.96 U2001.H2@962.83,3243.19
  Top w10: v1(513.43,3623.09) 512.53,3622.2 644.31,3490.42 644.31,3457.09 678.31,3423.09 755,3423.09 769,3409.09 v1(780.31,3409.09)
  Inner Layer 2 w8: v1(780.31,3409.09) 782.24,3411.02 797.17,3396.09 857.31,3396.09 886.31,3367.09 911.88,3367.09 939.31,3339.66 939.31,3336.09 948.31,3327.09 948.31,3286.37 953.61,3281.07 953.71,3281.07 v1(960.95,3273.83)
  Inner Layer 2 w12: v3(477.83,3619.53) 491.66,3619.53 496.22,3624.09 512.43,3624.09 v1(513.43,3623.09) ; v3(1606.31,4896.09) 1606.71,4896.48 1619.31,4883.87 1626.31,4876.87 v1(1626.31,4850.09)
  Inner Layer 4 w12: v3(477.83,3619.53) 461.81,3635.55 461.81,3646.48 424.31,3683.97 424.31,4119.41 542.74,4237.83 546.95,4237.83 547.42,4237.36 v3(562.56,4237.36)
  Inner Layer 5 w12: v3(562.56,4237.36) 598.21,4273.01 727.3,4273.01 818.38,4364.09 877.91,4364.09 907.91,4394.09 v2(920.31,4394.09) 923.91,4390.49 972.29,4390.49 1063.89,4482.09 1168.64,4482.09 1212.64,4526.09 1250.31,4526.09 1270.31,4546.09 1270.31,4744.43 1416.72,4890.83 1601.05,4890.83 v3(1606.31,4896.09)
  Bottom w12: R6203.2@902.45,4346.99 902.45,4347.99 903.3,4347.99 903.3,4377.08 v2(920.31,4394.09)
VCC1_PA: C3905.1 C3906.1 PA3901.1 R3904.2 | length 2197.3
  Top w12: R3904.2@1963.31,2851.56 1974.31,2840.56 v1(1974.31,2833.56)
  Inner Layer 2 w10: v3(2075.31,4275.09) 2131.42,4275.09 2152.05,4254.46 2263.45,4254.46 2318.31,4199.59 2318.31,4148.39 2484.86,3981.84 2484.86,3587.8 2461.95,3564.89 2461.95,3125.24 2426.05,3089.34 v3(2425.3,3090.09)
  Inner Layer 2 w12: v1(1974.31,2833.56) v3(1990.31,2833.56)
  Inner Layer 4 w10: v3(1990.31,2833.56) 1989.81,2834.06 2048.74,2834.06 2149.77,2935.09 2270.3,2935.09 v3(2425.3,3090.09)
  Inner Layer 5 w10: v2(2026.05,4291.33) 2042.29,4275.09 v3(2075.31,4275.09)
  Bottom w4: v2(2026.05,4291.33) 2025.85,4291.31 2023.08,4291.11 2024.31,4289.88 C3905.1@2026.08,4288.11 ; C3905.1@2027.08,4288.11 C3905.1@2031.08,4292.11
  Bottom w12: PA3901.1@1990.56,4289.88 2024.31,4289.88 2026.08,4289.88 C3905.1@2026.08,4288.11 C3905.1@2027.08,4288.11 ; v2(2026.05,4291.33) 2026.99,4288.4 C3905.1@2027.08,4288.11 ; C3906.1@2028.08,4262.11 2028.08,4288.11 C3905.1@2027.08,4288.11
VCC2_PA: C3908.1 C3909.1 C3910.1 PA3901.10 R3905.2 R3906.2 | length 2640.4
  Top w20: v1(1954.08,2787.58) 1954.08,2772.79 1963.31,2763.56 R3906.2@1963.31,2741.56
  Inner Layer 2 w4: v3(2489.73,3125.36) 2491.03,3125.36 v3@2491.31,3125.07
  Inner Layer 2 w40: v3(2064.68,4308.89) v3(2082.68,4308.89) 2138.7,4308.89 2163.94,4283.65 2264.15,4283.65 2264.33,4283.83 2275.7,4283.83 2308.44,4251.09 2308.81,4251.09 2346.31,4213.58 2346.31,4210.48 2347.31,4209.48 2347.31,4160.44 2514.33,3993.42 2514.33,3575.5 2491.31,3552.48 v3@2491.31,3153.02 ; v3(2491.02,3148.79) v3@2491.31,3150.44 ; v3@2491.31,3125.07 v3@2491.31,3150.44 ; v3@2491.31,3150.44 2491.86,3153.57 v3@2491.31,3153.02 ; v3@2491.31,3150.44 v3@2491.31,3153.02
  Inner Layer 4 w20: v3(1981.31,2780.56) v3(2001.31,2780.56)
  Inner Layer 4 w40: v3@1982.3,2777.56 1998.31,2777.56 v3(2001.31,2780.56) 2041.37,2780.56 2162.97,2902.16 2284.04,2902.16 2491.3,3109.42 2491.3,3148.51 v3(2491.02,3148.79)
  Inner Layer 5 w12: v2(2016.31,4392.09) v2(2016.31,4380.09) 2016.31,4356.09 2051.31,4321.09 2065.31,4321.09 ; v2(2029.31,4380.09) 2029.03,4380.09 2029.03,4392.35 v2(2028.74,4392.35) 2028.74,4366.09 2065.31,4329.52 2065.31,4321.09 ; v3(2064.68,4308.89) 2071.9,4313.71 2070.31,4316.09 2065.31,4316.09 2065.31,4321.09 ; 2067.1,4321.09 2065.31,4321.09
  Bottom w4: v2@2015.31,4386.33 2019.09,4390.11 C3908.1@2026.08,4390.11 ; v2(2016.31,4380.09) 2017.31,4380.09 2017.31,4381.09 2016.49,4381.22 1991.31,4385.09 PA3901.10@1991.31,4385.58 ; C3908.1@2021.08,4383.11 2021.08,4385.11 C3908.1@2026.08,4390.11 ; C3908.1@2021.08,4395.11 C3908.1@2026.08,4390.11 ; C3908.1@2026.08,4391.11 C3908.1@2029.08,4394.11 ; C3910.1@2026.08,4419.11 C3910.1@2028.03,4419.11 ; v2(2028.74,4392.35) 2028.16,4392.93 2026.57,4391.34 2026.08,4390.85 C3908.1@2026.08,4390.11 ; PA3901.10@1991.31,4385.58 PA3901.10@1990.56,4386.34 PA3901.10@1991.31,4385.58
  Bottom w12: C3909.1@2003.08,4419.11 C3910.1@2026.08,4419.11 2026.08,4392.35 2026.08,4392.09 C3908.1@2026.08,4391.11 ; 2008.31,4386.33 v2@2015.31,4386.33 ; C3908.1@2026.08,4390.85 C3908.1@2026.08,4391.11 ; v2(2028.74,4392.35) 2026.57,4391.34 C3908.1@2026.08,4391.11 ; PA3901.10@1990.56,4386.34 2008.08,4386.33 PA3901.10@1990.56,4386.34
  other v1: 1966.31,2772.56 1954.31,2773.56 1966.31,2787.56
VCDT: R2032.2 R2033.1 U2001.R1 | length 571.5
  Top w4: v1(797.9,3321.42) 805.25,3314.07 805.25,3310.37 806.31,3309.31 ; R2033.1@798.31,3322.09 806.31,3322.09 806.31,3309.31 ; U2001.R1@852.59,3258.94 846.27,3265.26 846.27,3269.35 806.31,3309.31
  Inner Layer 2 w4: v1(797.9,3321.42) 814.95,3304.37 v3(814.95,3303.83)
  Inner Layer 5 w4: v2(800.31,3319.09) 814.95,3304.45 v3(814.95,3303.83)
  Bottom w4: R2032.2@469.31,3499.09 473.31,3499.09 487.31,3485.09 487.31,3461.02 592.25,3356.09 752.16,3356.09 789.16,3319.09 v2(800.31,3319.09)
VCN18_PMU: C5015.2 R1031.2 SH5001.2 SH5002.2 U2001.F3 | length 2697.5
  Top w4: v1(778.95,4250.83) 783.95,4245.83 R1031.2@784.95,4245.83 ; SH5001.2@852.23,4405.26 852.23,4407.49 v1(855.66,4407.49)
  Top w12: v1(531.31,3625.09) 659.31,3497.09 659.31,3464.09 684.57,3438.83 762.06,3438.83 770.06,3430.83 782.57,3430.83 v1(803.31,3410.09) ; C5015.2@756.95,4250.83 v1(778.95,4250.83) ; v1(1122.31,4484.09) 1127.31,4489.09 SH5002.2@1138.31,4489.09
  Inner Layer 2 w4: 760.47,4250.83 761.21,4250.09
  Inner Layer 2 w8: v1(803.31,3410.09) 816.31,3410.09 818.31,3408.09 864,3408.09 893,3379.09 944.59,3379.09 977.99,3345.69 978.49,3345.69 986.25,3337.93 986.25,3337.22 990.31,3333.15 990.31,3259.71 980.32,3249.72 980.32,3238.81 991.69,3227.44 v4(994.32,3227.44)
  Inner Layer 2 w12: v3(529.3,3603.09) 530.31,3603.09 530.31,3625.09 v1(531.31,3625.09) ; v3(612.6,4308.04) 612.6,4283.09 620.86,4274.83 739.95,4274.83 764.69,4250.09 778.21,4250.09 v1(778.95,4250.83) ; v3(845.21,4387.07) 842.52,4389.76 857.95,4405.2 v1(855.66,4407.49) ; v3(1116.31,4501.09) 1122.31,4495.09 v1(1122.31,4484.09)
  Inner Layer 4 w12: v3(529.3,3603.09) 529.3,3584.64 496.75,3552.09 441.68,3552.09 372.31,3621.46 372.31,4140.94 539.41,4308.04 v3(612.6,4308.04) ; v3(845.21,4387.07) 844.79,4387.48 925.4,4468.09 1042.43,4468.09 1075.43,4501.09 v3(1116.31,4501.09)
  Inner Layer 5 w12: v3(612.6,4308.04) 715.9,4308.04 811.95,4404.09 831.02,4404.09 846.62,4388.48 v3(845.21,4387.07)
VCN28_PMU: BEAD5001.2 C5001.1 R5003.2 R5008.2 U2001.R13 | length 2324.7
  Top w4: R5003.2@829.95,4418.49 R5003.2@830.95,4418.49 ; C5001.1@830.95,4395.49 R5003.2@830.95,4418.49 ; BEAD5001.2@847.31,4558.09 848.31,4559.09 BEAD5001.2@849.31,4559.09 850.31,4560.09 854.03,4560.09 v1(855.04,4555.83) ; v1(856.07,4450.24) R5008.2@856.08,4450.11 ; R5008.2@857.08,4450.11 R5008.2@856.08,4450.11 ; R5003.2@830.95,4418.49 830.95,4424.98 R5008.2@856.08,4450.11
  Top w6: 782.95,3074.83 789.21,3081.09 841.46,3081.09 U2001.R13@852.59,3069.96
  Top w8: 707.95,3066.09 774.21,3066.09 782.95,3074.83
  Top w10: v1(422.95,3641.83) 436.17,3641.83 449.31,3628.68 449.31,3196.52 586.82,3059.02 700.88,3059.02 707.95,3066.09
  Inner Layer 2 w12: v1(422.95,3641.83) 416.95,3647.83 416.95,4082.46 440.32,4105.83 440.56,4105.83 539.95,4205.22 539.95,4243.13 593.31,4296.49 593.31,4392.85 606.31,4405.85 606.31,4462.44 634.31,4490.44 653.97,4490.44 655.65,4490.39 v3(659.38,4491.8) ; v3(838.31,4554.09) 853.3,4554.09 v1(855.04,4555.83) ; v3(838.98,4490.76) 837.65,4489.44 856.07,4471.02 v1(856.07,4450.24)
  Inner Layer 4 w12: v3(659.38,4491.8) 658.22,4492.96 673.35,4508.09 761.31,4508.09 810.31,4557.09 838.31,4557.09 v3(838.31,4554.09)
  Inner Layer 5 w12: v3(838.31,4554.09) 838.31,4523.09 838.98,4522.43 v3(838.98,4490.76)
VCN33_PMU: C5006.2 C5007.2 U2001.R12 U5001.33 | length 2582.4
  Top w6: 769,3089.09 770,3090.09 848.21,3090.09 U2001.R12@852.59,3085.71
  Top w8: 762.79,3082.87 768.74,3088.83 769,3089.09 ; U5001.33@1048.45,4471.17 1048.45,4486.36 1060.08,4497.99 C5007.2@1060.08,4502.11 v1(1059.08,4502.11)
  Top w10: 689.31,3079.09 700.31,3079.09 700.95,3079.72 703.05,3081.83 761.74,3081.83 762.79,3082.87
  Top w12: v1(464.95,3534.83) 464.95,3202.1 587.96,3079.09 689.31,3079.09
  Inner Layer 2 w10: v1(1058.49,4566.77) 1059.08,4566.18 v1(1059.08,4502.11)
  Inner Layer 2 w12: v1(464.95,3534.83) 415.24,3534.83 413.5,3533.09 362.76,3533.09 347.31,3548.54 347.31,3931.16 360.95,3944.8 360.95,4105.66 428.12,4172.83 428.86,4172.09 447.03,4172.09 499.95,4225.01 499.95,4262.78 553.31,4316.14 553.31,4426.19 v3(555.95,4428.83) ; v3(1042.08,4574.11) 1051.15,4574.11 v1(1058.49,4566.77)
  Inner Layer 4 w12: v3(555.95,4428.83) 589.43,4428.83 626.31,4465.71 626.31,4487.92 662.48,4524.09 754.31,4524.09 829.31,4599.09 980.12,4599.09 1005.1,4574.11 v3(1042.08,4574.11)
VCORE_PMIC_FB: SH1006.1 U2001.C2 | length 681.7
  Top w4: v4(1041.57,3243.19) 1041.56,3243.43 1041.8,3243.43 v4(1041.57,3243.19)
  Inner Layer 2 w4: v4(1041.57,3243.19) 1041.56,3242.01 1056.95,3242.01 v3(1057.92,3245.96)
  Inner Layer 5 w4: v3(1057.92,3245.96) 1057.92,3258.53 1054.31,3262.14 1054.31,3293.31 1072.31,3311.31 1072.31,3417.38 1113.31,3458.38 1113.31,3468.71 1127.66,3483.06 v2(1132.64,3483.06)
  Bottom w4: v2(1132.64,3483.06) 1129.31,3486.39 1129.31,3535.38 1043.31,3621.38 1043.31,3718.17 1062.64,3737.49 1114.12,3737.49 1120.12,3743.49 SH1006.1@1146.95,3743.49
